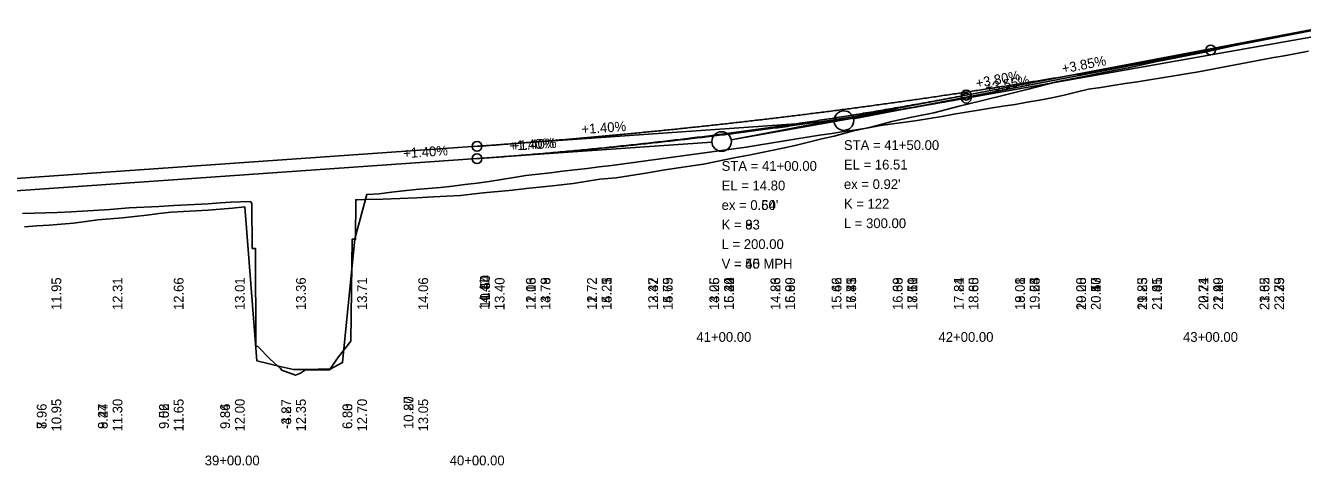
# Model space of a CAD drawing. Extents: x 3880794 to 3915434, y 287517 to 300173.
# Drawn here: x 3884354 to 3884876, y 296469 to 296649 of the extents above; entities that cross this region are included whole.
import ezdxf

# ---------------------------------------------------------------- set-up
doc = ezdxf.new("R2010")
doc.units = 0
for name, color, linetype in [('Level 1', 7, 'Continuous'), ('Level 2', 7, 'Continuous'), ('Level 30', 7, 'Continuous'), ('Level 31', 7, 'Continuous'), ('Level 32', 7, 'Continuous')]:
    doc.layers.add(name, color=color, linetype=linetype)

msp = doc.modelspace()

# ---------------------------------------------------------------- linework, layer by layer
at = {"layer": 'Level 1'}
for p, q in [((3884738.3, 296620.76), (3884888.3, 296649.26)), ((3884838.3, 296639.21), (3884888.3, 296648.85)), ((3884838.3, 296639.21), (3884692.23, 296611.06)), ((3884738.3, 296620.76), (3884642.23, 296602.5)), ((3884538.3, 296599.8), (3884684.31, 296610.03)), ((3884238.3, 296578.77), (3884538.3, 296599.8)), ((3884538.3, 296594.76), (3884634.31, 296601.48)), ((3884288.3, 296577.26), (3884538.3, 296594.76))]:
    msp.add_line(p, q, dxfattribs=at)
for points in [[(3884608.1, 296588.89), (3884614.3, 296590.03), (3884627.11, 296591.98), (3884630.89, 296592.44), (3884644.15, 296595.2), (3884650.18, 296596.32), (3884663.39, 296599.05), (3884668.41, 296600.07), (3884679.3, 296602.89), (3884684.29, 296603.99), (3884691.72, 296605.96), (3884699.38, 296607.62), (3884707.86, 296609.97), (3884716.01, 296611.74), (3884725.1, 296613.57), (3884735.46, 296616.27), (3884743.86, 296618.28), (3884745.01, 296618.58), (3884754.35, 296620.92), (3884763.15, 296623.1), (3884775.21, 296626.15), (3884784.31, 296627.94), (3884795.14, 296630.21), (3884805.15, 296632.12), (3884815.77, 296634.45), (3884824.79, 296636.1), (3884835.83, 296638.41), (3884846.92, 296640.83), (3884857.27, 296643.23), (3884866.44, 296644.96), (3884879.33, 296647.48)], [(3884352.46, 296572.25), (3884366.62, 296572.68), (3884372.44, 296572.99), (3884388.21, 296573.97), (3884396.11, 296574.61), (3884408.13, 296575.18), (3884414.31, 296575.61), (3884428.39, 296576.25), (3884433.24, 296576.71), (3884437.69, 296576.93), (3884445.65, 296577.2), (3884446.19, 296576.37), (3884446.38, 296558.01), (3884447.17, 296558.01), (3884447.71, 296558.01), (3884447.84, 296518.04), (3884448.67, 296517.86), (3884453.73, 296512.66), (3884457.89, 296508.85), (3884458.46, 296508.21), (3884464.14, 296506.07), (3884466.07, 296506.87), (3884468.12, 296508.3), (3884473.9, 296508.28), (3884478.01, 296508.27), (3884481.68, 296513.57), (3884486.66, 296520), (3884487.2, 296561.76), (3884487.51, 296561.76), (3884488.65, 296561.76), (3884488.73, 296577.95), (3884489.3, 296577.9), (3884492.51, 296577.98), (3884499.73, 296578.2), (3884513.63, 296578.76), (3884520.39, 296579.07), (3884531.6, 296579.7), (3884540.77, 296580.77), (3884551.47, 296581.7), (3884559.69, 296582.67), (3884569.1, 296583.69), (3884577.58, 296584.62), (3884588.44, 296586.36), (3884595.24, 296586.95), (3884608.1, 296588.89)]]:
    msp.add_lwpolyline(points, dxfattribs=at)
for centre in [(3884688.3, 296610.31), (3884638.3, 296601.76)]:
    msp.add_circle(centre, 4, dxfattribs=at)
for points in [[(3884538.3, 296599.8), (3884544.3, 296600.22), (3884550.3, 296600.67), (3884556.3, 296601.12), (3884562.3, 296601.6), (3884568.3, 296602.08), (3884574.3, 296602.58), (3884580.3, 296603.1), (3884586.3, 296603.63), (3884592.3, 296604.18), (3884598.3, 296604.74), (3884604.3, 296605.31), (3884610.3, 296605.9), (3884616.3, 296606.51), (3884622.3, 296607.12), (3884628.3, 296607.76), (3884634.3, 296608.41), (3884640.3, 296609.07), (3884646.3, 296609.75), (3884652.3, 296610.44), (3884658.3, 296611.15), (3884664.3, 296611.87), (3884670.3, 296612.61), (3884676.3, 296613.36), (3884682.3, 296614.12), (3884688.3, 296614.91), (3884694.3, 296615.7), (3884700.3, 296616.51), (3884706.3, 296617.34), (3884712.3, 296618.18), (3884718.3, 296619.03), (3884724.3, 296619.9), (3884730.3, 296620.79), (3884736.3, 296621.68), (3884742.3, 296622.6), (3884748.3, 296623.53), (3884754.3, 296624.47), (3884760.3, 296625.43), (3884766.3, 296626.4), (3884772.3, 296627.39), (3884778.3, 296628.39), (3884784.3, 296629.4), (3884790.3, 296630.43), (3884796.3, 296631.48), (3884802.3, 296632.54), (3884808.3, 296633.62), (3884814.3, 296634.71), (3884820.3, 296635.81), (3884826.3, 296636.93), (3884832.3, 296638.07), (3884838.3, 296639.21)], [(3884538.3, 296594.76), (3884542.3, 296595.04), (3884546.3, 296595.34), (3884550.3, 296595.64), (3884554.3, 296595.95), (3884558.3, 296596.28), (3884562.3, 296596.61), (3884566.3, 296596.95), (3884570.3, 296597.3), (3884574.3, 296597.67), (3884578.3, 296598.04), (3884582.3, 296598.42), (3884586.3, 296598.81), (3884590.3, 296599.21), (3884594.3, 296599.62), (3884598.3, 296600.04), (3884602.3, 296600.47), (3884606.3, 296600.9), (3884610.3, 296601.35), (3884614.3, 296601.81), (3884618.3, 296602.28), (3884622.3, 296602.75), (3884626.3, 296603.24), (3884630.3, 296603.74), (3884634.3, 296604.24), (3884638.3, 296604.76), (3884642.3, 296605.28), (3884646.3, 296605.82), (3884650.3, 296606.36), (3884654.3, 296606.91), (3884658.3, 296607.48), (3884662.3, 296608.05), (3884666.3, 296608.63), (3884670.3, 296609.22), (3884674.3, 296609.83), (3884678.3, 296610.44), (3884682.3, 296611.06), (3884686.3, 296611.69), (3884690.3, 296612.33), (3884694.3, 296612.98), (3884698.3, 296613.64), (3884702.3, 296614.31), (3884706.3, 296614.98), (3884710.3, 296615.67), (3884714.3, 296616.37), (3884718.3, 296617.08), (3884722.3, 296617.79), (3884726.3, 296618.52), (3884730.3, 296619.26), (3884734.3, 296620), (3884738.3, 296620.76)]]:
    msp.add_spline(points, degree=3, dxfattribs=at)
at = {"layer": 'Level 2'}
for p, q in [((3884738.3, 296619.51), (3884888.3, 296646.13)), ((3884738.3, 296619.51), (3884642.24, 296602.46)), ((3884538.3, 296594.76), (3884634.31, 296601.48)), ((3884338.3, 296580.76), (3884538.3, 296594.76))]:
    msp.add_line(p, q, dxfattribs=at)
for points in [[(3884538.3, 296584.75), (3884543.3, 296585.42), (3884548.3, 296586.21), (3884553.3, 296587), (3884558.3, 296587.79), (3884563.3, 296588.4), (3884568.3, 296589.01), (3884573.3, 296589.61), (3884578.3, 296590.19), (3884583.3, 296590.78), (3884588.3, 296591.38), (3884593.3, 296592.01), (3884598.3, 296592.65), (3884603.3, 296593.28), (3884608.3, 296593.94), (3884613.3, 296594.61), (3884618.3, 296595.3), (3884623.3, 296595.99), (3884628.3, 296596.69), (3884633.3, 296597.38), (3884638.3, 296598.08), (3884643.3, 296598.77), (3884648.3, 296599.47), (3884653.3, 296600.23), (3884658.3, 296601.07), (3884663.3, 296601.91), (3884668.3, 296602.73), (3884673.3, 296603.52), (3884678.3, 296604.31), (3884683.3, 296605.07), (3884688.3, 296605.84), (3884693.3, 296606.61), (3884698.3, 296607.39), (3884703.3, 296608.26), (3884708.3, 296608.98), (3884713.3, 296609.71), (3884718.3, 296610.43), (3884723.3, 296611.21), (3884728.3, 296612.07), (3884733.3, 296612.93), (3884738.3, 296613.79), (3884743.3, 296614.6), (3884748.3, 296615.38), (3884753.3, 296616.17), (3884758.3, 296616.95), (3884763.3, 296617.82), (3884768.3, 296618.76), (3884773.3, 296619.69), (3884778.3, 296620.75), (3884783.3, 296621.97), (3884788.3, 296623.15), (3884793.3, 296623.9), (3884798.3, 296624.65), (3884803.3, 296625.45), (3884808.3, 296626.23), (3884813.3, 296627.01), (3884818.3, 296627.8), (3884823.3, 296628.65), (3884828.3, 296629.49), (3884833.3, 296630.34), (3884838.3, 296631.28), (3884843.3, 296632.22), (3884848.3, 296633.19), (3884853.3, 296634.14), (3884858.3, 296635.08), (3884863.3, 296636.01), (3884868.3, 296636.9), (3884873.3, 296637.84), (3884878.3, 296638.78)], [(3884353.3, 296566.87), (3884358.3, 296567.23), (3884363.3, 296567.55), (3884368.3, 296567.87), (3884373.3, 296568.39), (3884378.3, 296569.03), (3884383.3, 296569.65), (3884388.3, 296570.12), (3884393.3, 296570.58), (3884398.3, 296571.07), (3884403.3, 296571.68), (3884408.3, 296572.3), (3884413.3, 296572.87), (3884418.3, 296573.13), (3884423.3, 296573.4), (3884428.3, 296573.68), (3884433.3, 296574.11), (3884438.3, 296574.54), (3884443.3, 296574.97), (3884448.3, 296511.94), (3884453.3, 296510.73), (3884458.3, 296509.47), (3884463.3, 296508.4), (3884468.3, 296508.48), (3884473.3, 296508.51), (3884478.3, 296508.56), (3884483.3, 296511.26), (3884488.3, 296561.9), (3884493.3, 296580.08), (3884498.3, 296580.4), (3884503.3, 296581.02), (3884508.3, 296581.64), (3884513.3, 296582.1), (3884518.3, 296582.51), (3884523.3, 296582.93), (3884528.3, 296583.5), (3884533.3, 296584.13), (3884538.3, 296584.75)]]:
    msp.add_lwpolyline(points, dxfattribs=at)
for centre, radius in [((3884738.3, 296619.51), 2), ((3884638.3, 296601.76), 4), ((3884538.3, 296594.76), 2)]:
    msp.add_circle(centre, radius, dxfattribs=at)
msp.add_spline([(3884538.3, 296594.76), (3884542.3, 296595.04), (3884546.3, 296595.33), (3884550.3, 296595.64), (3884554.3, 296595.95), (3884558.3, 296596.26), (3884562.3, 296596.59), (3884566.3, 296596.93), (3884570.3, 296597.27), (3884574.3, 296597.63), (3884578.3, 296597.99), (3884582.3, 296598.36), (3884586.3, 296598.74), (3884590.3, 296599.12), (3884594.3, 296599.52), (3884598.3, 296599.92), (3884602.3, 296600.34), (3884606.3, 296600.76), (3884610.3, 296601.19), (3884614.3, 296601.63), (3884618.3, 296602.08), (3884622.3, 296602.53), (3884626.3, 296603), (3884630.3, 296603.47), (3884634.3, 296603.95), (3884638.3, 296604.44), (3884642.3, 296604.94), (3884646.3, 296605.45), (3884650.3, 296605.97), (3884654.3, 296606.49), (3884658.3, 296607.03), (3884662.3, 296607.57), (3884666.3, 296608.12), (3884670.3, 296608.68), (3884674.3, 296609.25), (3884678.3, 296609.82), (3884682.3, 296610.41), (3884686.3, 296611), (3884690.3, 296611.61), (3884694.3, 296612.22), (3884698.3, 296612.84), (3884702.3, 296613.47), (3884706.3, 296614.1), (3884710.3, 296614.75), (3884714.3, 296615.4), (3884718.3, 296616.06), (3884722.3, 296616.74), (3884726.3, 296617.42), (3884730.3, 296618.1), (3884734.3, 296618.8), (3884738.3, 296619.51)], degree=3, dxfattribs=at)
at = {"layer": 'Level 31'}
for centre in [(3884838.3, 296639.21), (3884738.3, 296620.76), (3884538.3, 296599.8), (3884538.3, 296594.76)]:
    msp.add_circle(centre, 2, dxfattribs=at)

# ---------------------------------------------------------------- texts
at = {"layer": 'Level 2'}
for s, rotation, p in [('+3.55%', 10.0652, (3884746.49, 296621.77)), ('+1.40%', 4.0042, (3884552.67, 296597.97)), ('+1.40%', 4.0042, (3884508.25, 296594.9)), ('13.40', 90, (3884549.54, 296532.72)), ('13.78', 90, (3884568.3, 296532.76)), ('14.23', 90, (3884593.3, 296532.76)), ('14.75', 90, (3884618.3, 296532.76)), ('15.34', 90, (3884643.3, 296532.76)), ('15.99', 90, (3884668.3, 296532.76)), ('16.71', 90, (3884693.3, 296532.76)), ('17.50', 90, (3884718.3, 296532.76)), ('18.35', 90, (3884743.3, 296532.76)), ('19.24', 90, (3884768.3, 296532.76)), ('20.13', 90, (3884793.3, 296532.76)), ('21.01', 90, (3884818.3, 296532.76)), ('21.90', 90, (3884843.3, 296532.76)), ('22.79', 90, (3884868.3, 296532.76)), ('10.95', 90, (3884368.3, 296483.07)), ('11.30', 90, (3884393.3, 296483.07)), ('11.65', 90, (3884418.3, 296483.07)), ('12.00', 90, (3884443.3, 296483.07)), ('12.35', 90, (3884468.3, 296483.07)), ('12.70', 90, (3884493.3, 296483.07)), ('13.05', 90, (3884518.3, 296483.07))]:
    msp.add_text(s, height=4, rotation=rotation, dxfattribs=at).set_placement(p)
for s, p in [('STA = 41+00.00', (3884638.3, 296589.76)), ('EL = 14.80', (3884638.3, 296581.76)), ("ex = 0.54'", (3884638.3, 296573.76)), ('K = 93', (3884638.3, 296565.76)), ('L = 200.00', (3884638.3, 296557.76)), ('V = 50 MPH', (3884638.3, 296549.76)), ('41+00.00', (3884628, 296519.76)), ('42+00.00', (3884726.99, 296519.76)), ('43+00.00', (3884826.96, 296519.76)), ('39+00.00', (3884426.96, 296469.2)), ('40+00.00', (3884527.12, 296469.2))]:
    msp.add_text(s, height=4, dxfattribs=at).set_placement(p)
at = {"layer": 'Level 30'}
for s, p in [('10.54', (3884543.54, 296533.73)), ('11.06', (3884562.3, 296532.76)), ('11.72', (3884587.3, 296532.76)), ('12.42', (3884612.3, 296532.76)), ('13.25', (3884637.3, 296532.76)), ('14.26', (3884662.3, 296532.76)), ('15.46', (3884687.3, 296532.76)), ('16.68', (3884712.3, 296532.76)), ('17.84', (3884737.3, 296532.76)), ('19.08', (3884762.3, 296532.76)), ('20.20', (3884787.3, 296532.76)), ('21.23', (3884812.3, 296532.76)), ('22.24', (3884837.3, 296532.76)), ('23.32', (3884862.3, 296532.76)), ('8.96', (3884362.3, 296484.08)), ('9.24', (3884387.3, 296484.08)), ('9.56', (3884412.3, 296484.08)), ('9.84', (3884437.3, 296484.08)), ('-4.27', (3884462.3, 296484.08)), ('6.80', (3884487.3, 296484.08)), ('10.20', (3884512.3, 296484.08))]:
    msp.add_text(s, height=4, rotation=90, dxfattribs=at).set_placement(p)
for s, p in [('41+00.00', (3884628, 296519.76)), ('41+00.00', (3884628, 296519.76)), ('41+00.00', (3884628, 296519.76)), ('42+00.00', (3884726.99, 296519.76)), ('42+00.00', (3884726.99, 296519.76)), ('42+00.00', (3884726.99, 296519.76)), ('43+00.00', (3884826.96, 296519.76)), ('43+00.00', (3884826.96, 296519.76)), ('43+00.00', (3884826.96, 296519.76)), ('39+00.00', (3884426.96, 296469.2)), ('40+00.00', (3884527.12, 296469.2))]:
    msp.add_text(s, height=4, dxfattribs=at).set_placement(p)
at = {"layer": 'Level 31'}
for s, rotation, p in [('+3.85%', 10.908, (3884777.82, 296629.6)), ('+3.80%', 10.758, (3884742.63, 296623.56)), ('+1.40%', 4.0086, (3884581.14, 296604.8)), ('+1.40%', 4.0042, (3884551.65, 296597.97)), ('11.95', 90, (3884368.3, 296532.76)), ('12.31', 90, (3884393.3, 296532.76)), ('12.66', 90, (3884418.3, 296532.76)), ('13.01', 90, (3884443.3, 296532.76)), ('13.36', 90, (3884468.3, 296532.76)), ('13.71', 90, (3884493.3, 296532.76)), ('14.06', 90, (3884518.3, 296532.76)), ('14.41', 90, (3884543.3, 296532.76)), ('13.40', 90, (3884549.54, 296532.72)), ('14.78', 90, (3884568.3, 296532.76)), ('13.79', 90, (3884568.3, 296532.76)), ('14.25', 90, (3884593.3, 296532.76)), ('15.21', 90, (3884593.3, 296532.76)), ('14.79', 90, (3884618.3, 296532.76)), ('15.69', 90, (3884618.3, 296532.76)), ('15.40', 90, (3884643.3, 296532.76)), ('16.22', 90, (3884643.3, 296532.76)), ('16.80', 90, (3884668.3, 296532.76)), ('16.09', 90, (3884668.3, 296532.76)), ('16.85', 90, (3884693.3, 296532.76)), ('17.43', 90, (3884693.3, 296532.76)), ('17.69', 90, (3884718.3, 296532.76)), ('18.11', 90, (3884718.3, 296532.76)), ('18.60', 90, (3884743.3, 296532.76)), ('18.85', 90, (3884743.3, 296532.76)), ('19.55', 90, (3884768.3, 296532.76)), ('19.63', 90, (3884768.3, 296532.76)), ('20.50', 90, (3884793.3, 296532.76)), ('20.47', 90, (3884793.3, 296532.76)), ('21.45', 90, (3884818.3, 296532.76)), ('21.35', 90, (3884818.3, 296532.76)), ('22.40', 90, (3884843.3, 296532.76)), ('22.29', 90, (3884843.3, 296532.76)), ('23.35', 90, (3884868.3, 296532.76)), ('23.25', 90, (3884868.3, 296532.76)), ('10.95', 90, (3884368.3, 296483.07)), ('11.30', 90, (3884393.3, 296483.07)), ('11.65', 90, (3884418.3, 296483.07)), ('12.00', 90, (3884443.3, 296483.07)), ('12.35', 90, (3884468.3, 296483.07)), ('12.70', 90, (3884493.3, 296483.07)), ('13.05', 90, (3884518.3, 296483.07))]:
    msp.add_text(s, height=4, rotation=rotation, dxfattribs=at).set_placement(p)
for s, p in [('STA = 41+50.00', (3884688.3, 296598.31)), ('STA = 41+00.00', (3884638.3, 296589.76)), ('EL = 16.51', (3884688.3, 296590.31)), ('EL = 14.80', (3884638.3, 296581.76)), ("ex = 0.92'", (3884688.3, 296582.31)), ("ex = 0.60'", (3884638.3, 296573.76)), ('K = 122', (3884688.3, 296574.31)), ('K = 83', (3884638.3, 296565.76)), ('L = 300.00', (3884688.3, 296566.31)), ('L = 200.00', (3884638.3, 296557.76)), ('V = 45 MPH', (3884638.3, 296549.76))]:
    msp.add_text(s, height=4, dxfattribs=at).set_placement(p)
at = {"layer": 'Level 32'}
for s, p in [('11.40', (3884543.54, 296533.73)), ('12.13', (3884562.3, 296532.76)), ('12.72', (3884587.3, 296532.76)), ('13.37', (3884612.3, 296532.76)), ('14.06', (3884637.3, 296532.76)), ('14.83', (3884662.3, 296532.76)), ('15.62', (3884687.3, 296532.76)), ('16.39', (3884712.3, 296532.76)), ('17.21', (3884737.3, 296532.76)), ('18.01', (3884762.3, 296532.76)), ('19.08', (3884787.3, 296532.76)), ('19.85', (3884812.3, 296532.76)), ('20.71', (3884837.3, 296532.76)), ('21.65', (3884862.3, 296532.76)), ('7.96', (3884362.3, 296484.08)), ('8.47', (3884387.3, 296484.08)), ('9.02', (3884412.3, 296484.08)), ('9.36', (3884437.3, 296484.08)), ('-3.87', (3884462.3, 296484.08)), ('6.83', (3884487.3, 296484.08)), ('10.87', (3884512.3, 296484.08))]:
    msp.add_text(s, height=4, rotation=90, dxfattribs=at).set_placement(p)

doc.saveas('drawing.dxf')
